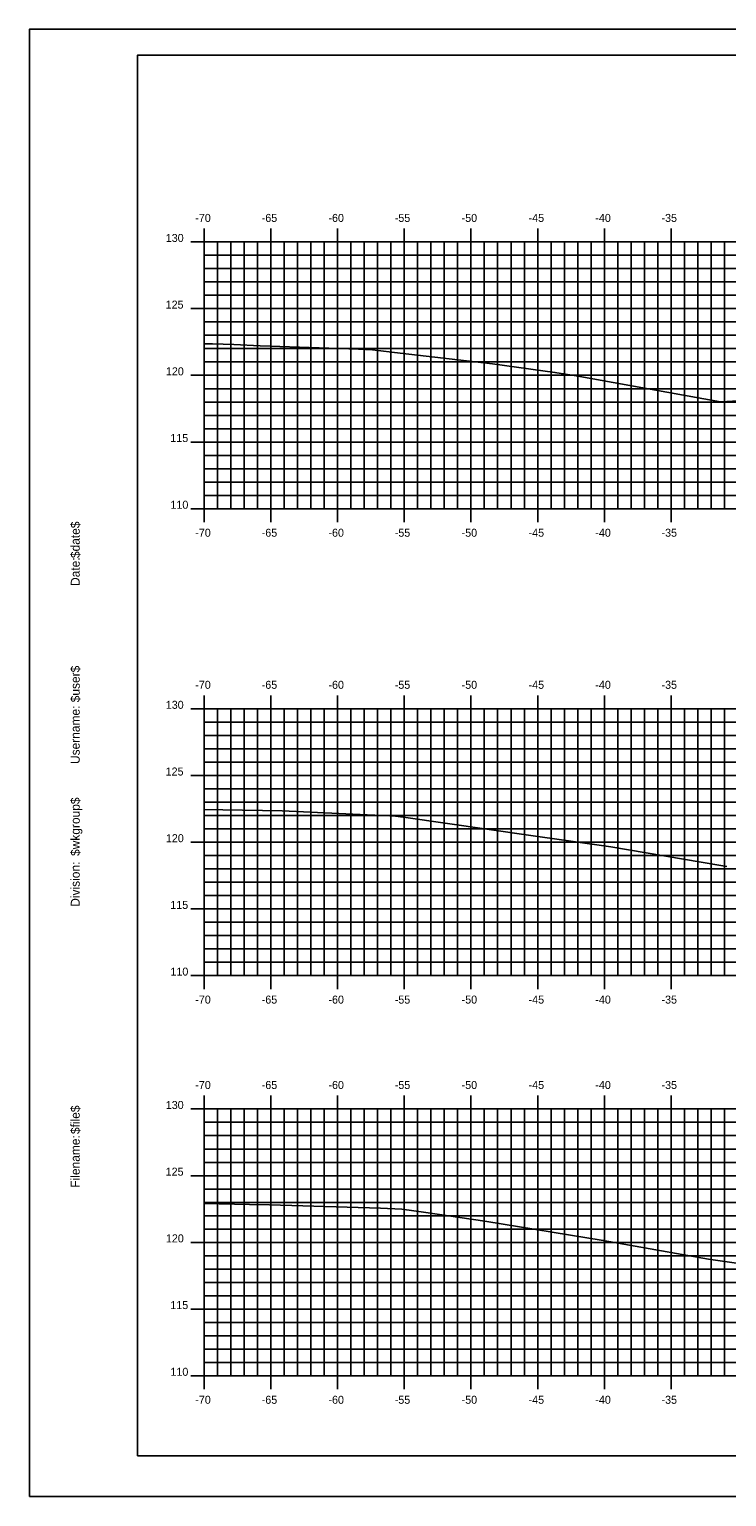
# Model space of a CAD drawing. Extents: x 852625 to 852797, y 365624 to 365734.
# Drawn here: x 852625.5 to 852677.7, y 365624 to 365734 of the extents above; entities that cross this region are included whole.
import ezdxf

# ---------------------------------------------------------------- set-up
doc = ezdxf.new("R2010")
doc.units = 0
for name, color, linetype in [('BORDER', 7, 'Continuous'), ('H_V ANNOTATION', 7, 'Continuous'), ('MAJOR', 7, 'Continuous'), ('MINOR', 7, 'Continuous'), ('PLOT BOUNDARY', 7, 'Continuous'), ('S_Roadway_Centerline', 7, 'Continuous')]:
    doc.layers.add(name, color=color, linetype=linetype)

msp = doc.modelspace()

# ---------------------------------------------------------------- linework, layer by layer
at = {"layer": 'BORDER'}
msp.add_lwpolyline([(852633.55, 365627.03), (852793.55, 365627.03), (852793.55, 365732.03), (852633.55, 365732.03)], close=True, dxfattribs=at)
at = {"layer": 'MAJOR'}
for p, q in [((852638.55, 365719.03), (852638.55, 365718.03)), ((852643.55, 365719.03), (852643.55, 365718.03)), ((852648.55, 365719.03), (852648.55, 365718.03)), ((852653.55, 365719.03), (852653.55, 365718.03)), ((852658.55, 365719.03), (852658.55, 365718.03)), ((852663.55, 365719.03), (852663.55, 365718.03)), ((852668.55, 365719.03), (852668.55, 365718.03)), ((852673.55, 365719.03), (852673.55, 365718.03)), ((852637.55, 365718.03), (852638.55, 365718.03)), ((852638.55, 365718.03), (852778.55, 365718.03)), ((852638.55, 365698.03), (852638.55, 365718.03)), ((852638.55, 365698.03), (852638.55, 365718.03)), ((852638.55, 365718.03), (852778.55, 365718.03)), ((852643.55, 365698.03), (852643.55, 365718.03)), ((852648.55, 365698.03), (852648.55, 365718.03)), ((852653.55, 365698.03), (852653.55, 365718.03)), ((852658.55, 365698.03), (852658.55, 365718.03)), ((852663.55, 365698.03), (852663.55, 365718.03)), ((852668.55, 365698.03), (852668.55, 365718.03)), ((852673.55, 365698.03), (852673.55, 365718.03)), ((852637.55, 365713.03), (852638.55, 365713.03)), ((852638.55, 365713.03), (852778.55, 365713.03)), ((852637.55, 365708.03), (852638.55, 365708.03)), ((852638.55, 365708.03), (852778.55, 365708.03)), ((852637.55, 365703.03), (852638.55, 365703.03)), ((852638.55, 365703.03), (852778.55, 365703.03)), ((852637.55, 365698.03), (852638.55, 365698.03)), ((852638.55, 365698.03), (852778.55, 365698.03)), ((852638.55, 365697.02), (852638.55, 365698.03)), ((852643.55, 365697.02), (852643.55, 365698.03)), ((852648.55, 365697.02), (852648.55, 365698.03)), ((852653.55, 365697.02), (852653.55, 365698.03)), ((852658.55, 365697.02), (852658.55, 365698.03)), ((852663.55, 365697.02), (852663.55, 365698.03)), ((852668.55, 365697.02), (852668.55, 365698.03)), ((852673.55, 365697.02), (852673.55, 365698.03)), ((852638.55, 365684.03), (852638.55, 365683.03)), ((852643.55, 365684.03), (852643.55, 365683.03)), ((852648.55, 365684.03), (852648.55, 365683.03)), ((852653.55, 365684.03), (852653.55, 365683.03)), ((852658.55, 365684.03), (852658.55, 365683.03)), ((852663.55, 365684.03), (852663.55, 365683.03)), ((852668.55, 365684.03), (852668.55, 365683.03)), ((852673.55, 365684.03), (852673.55, 365683.03)), ((852637.55, 365683.03), (852638.55, 365683.03)), ((852638.55, 365683.03), (852778.55, 365683.03)), ((852638.55, 365663.03), (852638.55, 365683.03)), ((852638.55, 365663.03), (852638.55, 365683.03)), ((852638.55, 365683.03), (852778.55, 365683.03)), ((852643.55, 365663.03), (852643.55, 365683.03)), ((852648.55, 365663.03), (852648.55, 365683.03)), ((852653.55, 365663.03), (852653.55, 365683.03)), ((852658.55, 365663.03), (852658.55, 365683.03)), ((852663.55, 365663.03), (852663.55, 365683.03)), ((852668.55, 365663.03), (852668.55, 365683.03)), ((852673.55, 365663.03), (852673.55, 365683.03)), ((852637.55, 365678.03), (852638.55, 365678.03)), ((852638.55, 365678.03), (852778.55, 365678.03)), ((852637.55, 365673.03), (852638.55, 365673.03)), ((852638.55, 365673.03), (852778.55, 365673.03)), ((852637.55, 365668.03), (852638.55, 365668.03)), ((852638.55, 365668.03), (852778.55, 365668.03)), ((852637.55, 365663.03), (852638.55, 365663.03)), ((852638.55, 365663.03), (852778.55, 365663.03)), ((852638.55, 365663.03), (852778.55, 365663.03)), ((852638.55, 365662.02), (852638.55, 365663.03)), ((852643.55, 365662.02), (852643.55, 365663.03)), ((852648.55, 365662.02), (852648.55, 365663.03)), ((852653.55, 365662.02), (852653.55, 365663.03)), ((852658.55, 365662.02), (852658.55, 365663.03)), ((852663.55, 365662.02), (852663.55, 365663.03)), ((852668.55, 365662.02), (852668.55, 365663.03)), ((852673.55, 365662.02), (852673.55, 365663.03)), ((852638.55, 365654.03), (852638.55, 365653.03)), ((852643.55, 365654.03), (852643.55, 365653.03)), ((852648.55, 365654.03), (852648.55, 365653.03)), ((852653.55, 365654.03), (852653.55, 365653.03)), ((852658.55, 365654.03), (852658.55, 365653.03)), ((852663.55, 365654.03), (852663.55, 365653.03)), ((852668.55, 365654.03), (852668.55, 365653.03)), ((852673.55, 365654.03), (852673.55, 365653.03)), ((852637.55, 365653.03), (852638.55, 365653.03)), ((852638.55, 365653.03), (852778.55, 365653.03)), ((852638.55, 365633.03), (852638.55, 365653.03)), ((852638.55, 365633.03), (852638.55, 365653.03)), ((852638.55, 365653.03), (852778.55, 365653.03)), ((852643.55, 365633.03), (852643.55, 365653.03)), ((852648.55, 365633.03), (852648.55, 365653.03)), ((852653.55, 365633.03), (852653.55, 365653.03)), ((852658.55, 365633.03), (852658.55, 365653.03)), ((852663.55, 365633.03), (852663.55, 365653.03)), ((852668.55, 365633.03), (852668.55, 365653.03)), ((852673.55, 365633.03), (852673.55, 365653.03)), ((852637.55, 365648.03), (852638.55, 365648.03)), ((852638.55, 365648.03), (852778.55, 365648.03)), ((852637.55, 365643.03), (852638.55, 365643.03)), ((852638.55, 365643.03), (852778.55, 365643.03)), ((852637.55, 365638.03), (852638.55, 365638.03)), ((852638.55, 365638.03), (852778.55, 365638.03)), ((852637.55, 365633.03), (852638.55, 365633.03)), ((852638.55, 365633.03), (852778.55, 365633.03)), ((852638.55, 365633.03), (852778.55, 365633.03)), ((852638.55, 365632.02), (852638.55, 365633.03)), ((852643.55, 365632.02), (852643.55, 365633.03)), ((852648.55, 365632.02), (852648.55, 365633.03)), ((852653.55, 365632.02), (852653.55, 365633.03)), ((852658.55, 365632.02), (852658.55, 365633.03)), ((852663.55, 365632.02), (852663.55, 365633.03)), ((852668.55, 365632.02), (852668.55, 365633.03)), ((852673.55, 365632.02), (852673.55, 365633.03))]:
    msp.add_line(p, q, dxfattribs=at)
at = {"layer": 'MINOR'}
for p, q in [((852638.55, 365698.03), (852638.55, 365718.03)), ((852638.55, 365717.03), (852778.55, 365717.03)), ((852638.55, 365717.03), (852639.55, 365717.03)), ((852639.55, 365698.03), (852639.55, 365718.03)), ((852640.55, 365698.03), (852640.55, 365718.03)), ((852641.55, 365698.03), (852641.55, 365718.03)), ((852642.55, 365698.03), (852642.55, 365718.03)), ((852644.55, 365698.03), (852644.55, 365718.03)), ((852645.55, 365698.03), (852645.55, 365718.03)), ((852646.55, 365698.03), (852646.55, 365718.03)), ((852647.55, 365698.03), (852647.55, 365718.03)), ((852649.55, 365698.03), (852649.55, 365718.03)), ((852650.55, 365698.03), (852650.55, 365718.03)), ((852651.55, 365698.03), (852651.55, 365718.03)), ((852652.55, 365698.03), (852652.55, 365718.03)), ((852654.55, 365698.03), (852654.55, 365718.03)), ((852655.55, 365698.03), (852655.55, 365718.03)), ((852656.55, 365698.03), (852656.55, 365718.03)), ((852657.55, 365698.03), (852657.55, 365718.03)), ((852659.55, 365698.03), (852659.55, 365718.03)), ((852660.55, 365698.03), (852660.55, 365718.03)), ((852661.55, 365698.03), (852661.55, 365718.03)), ((852662.55, 365698.03), (852662.55, 365718.03)), ((852664.55, 365698.03), (852664.55, 365718.03)), ((852665.55, 365698.03), (852665.55, 365718.03)), ((852666.55, 365698.03), (852666.55, 365718.03)), ((852667.55, 365698.03), (852667.55, 365718.03)), ((852669.55, 365698.03), (852669.55, 365718.03)), ((852670.55, 365698.03), (852670.55, 365718.03)), ((852671.55, 365698.03), (852671.55, 365718.03)), ((852672.55, 365698.03), (852672.55, 365718.03)), ((852674.55, 365698.03), (852674.55, 365718.03)), ((852675.55, 365698.03), (852675.55, 365718.03)), ((852676.55, 365698.03), (852676.55, 365718.03)), ((852677.55, 365698.03), (852677.55, 365718.03)), ((852638.55, 365716.03), (852778.55, 365716.03)), ((852638.55, 365716.03), (852639.55, 365716.03)), ((852638.55, 365715.03), (852778.55, 365715.03)), ((852638.55, 365715.03), (852639.55, 365715.03)), ((852638.55, 365714.03), (852778.55, 365714.03)), ((852638.55, 365714.03), (852639.55, 365714.03)), ((852638.55, 365712.03), (852778.55, 365712.03)), ((852638.55, 365712.03), (852639.55, 365712.03)), ((852638.55, 365711.03), (852778.55, 365711.03)), ((852638.55, 365711.03), (852639.55, 365711.03)), ((852638.55, 365710.03), (852778.55, 365710.03)), ((852638.55, 365710.03), (852639.55, 365710.03)), ((852638.55, 365709.03), (852778.55, 365709.03)), ((852638.55, 365709.03), (852639.55, 365709.03)), ((852638.55, 365707.03), (852778.55, 365707.03)), ((852638.55, 365707.03), (852639.55, 365707.03)), ((852638.55, 365706.03), (852778.55, 365706.03)), ((852638.55, 365706.03), (852639.55, 365706.03)), ((852638.55, 365705.03), (852778.55, 365705.03)), ((852638.55, 365705.03), (852639.55, 365705.03)), ((852638.55, 365704.03), (852778.55, 365704.03)), ((852638.55, 365704.03), (852639.55, 365704.03)), ((852638.55, 365702.03), (852778.55, 365702.03)), ((852638.55, 365702.03), (852639.55, 365702.03)), ((852638.55, 365701.03), (852778.55, 365701.03)), ((852638.55, 365701.03), (852639.55, 365701.03)), ((852638.55, 365700.03), (852778.55, 365700.03)), ((852638.55, 365700.03), (852639.55, 365700.03)), ((852638.55, 365699.03), (852778.55, 365699.03)), ((852638.55, 365699.03), (852639.55, 365699.03)), ((852639.55, 365663.03), (852639.55, 365683.03)), ((852640.55, 365663.03), (852640.55, 365683.03)), ((852641.55, 365663.03), (852641.55, 365683.03)), ((852642.55, 365663.03), (852642.55, 365683.03)), ((852644.55, 365663.03), (852644.55, 365683.03)), ((852645.55, 365663.03), (852645.55, 365683.03)), ((852646.55, 365663.03), (852646.55, 365683.03)), ((852647.55, 365663.03), (852647.55, 365683.03)), ((852649.55, 365663.03), (852649.55, 365683.03)), ((852650.55, 365663.03), (852650.55, 365683.03)), ((852651.55, 365663.03), (852651.55, 365683.03)), ((852652.55, 365663.03), (852652.55, 365683.03)), ((852654.55, 365663.03), (852654.55, 365683.03)), ((852655.55, 365663.03), (852655.55, 365683.03)), ((852656.55, 365663.03), (852656.55, 365683.03)), ((852657.55, 365663.03), (852657.55, 365683.03)), ((852659.55, 365663.03), (852659.55, 365683.03)), ((852660.55, 365663.03), (852660.55, 365683.03)), ((852661.55, 365663.03), (852661.55, 365683.03)), ((852662.55, 365663.03), (852662.55, 365683.03)), ((852664.55, 365663.03), (852664.55, 365683.03)), ((852665.55, 365663.03), (852665.55, 365683.03)), ((852666.55, 365663.03), (852666.55, 365683.03)), ((852667.55, 365663.03), (852667.55, 365683.03)), ((852669.55, 365663.03), (852669.55, 365683.03)), ((852670.55, 365663.03), (852670.55, 365683.03)), ((852671.55, 365663.03), (852671.55, 365683.03)), ((852672.55, 365663.03), (852672.55, 365683.03)), ((852674.55, 365663.03), (852674.55, 365683.03)), ((852675.55, 365663.03), (852675.55, 365683.03)), ((852676.55, 365663.03), (852676.55, 365683.03)), ((852677.55, 365663.03), (852677.55, 365683.03)), ((852638.55, 365682.03), (852778.55, 365682.03)), ((852638.55, 365682.03), (852639.55, 365682.03)), ((852638.55, 365681.03), (852778.55, 365681.03)), ((852638.55, 365681.03), (852639.55, 365681.03)), ((852638.55, 365680.03), (852778.55, 365680.03)), ((852638.55, 365680.03), (852639.55, 365680.03)), ((852638.55, 365679.03), (852778.55, 365679.03)), ((852638.55, 365679.03), (852639.55, 365679.03)), ((852638.55, 365677.03), (852778.55, 365677.03)), ((852638.55, 365677.03), (852639.55, 365677.03)), ((852638.55, 365676.03), (852778.55, 365676.03)), ((852638.55, 365676.03), (852639.55, 365676.03)), ((852638.55, 365675.03), (852778.55, 365675.03)), ((852638.55, 365675.03), (852639.55, 365675.03)), ((852638.55, 365674.03), (852778.55, 365674.03)), ((852638.55, 365674.03), (852639.55, 365674.03)), ((852638.55, 365672.03), (852778.55, 365672.03)), ((852638.55, 365672.03), (852639.55, 365672.03)), ((852638.55, 365671.03), (852778.55, 365671.03)), ((852638.55, 365671.03), (852639.55, 365671.03)), ((852638.55, 365670.03), (852778.55, 365670.03)), ((852638.55, 365670.03), (852639.55, 365670.03)), ((852638.55, 365669.03), (852778.55, 365669.03)), ((852638.55, 365669.03), (852639.55, 365669.03)), ((852638.55, 365667.03), (852778.55, 365667.03)), ((852638.55, 365667.03), (852639.55, 365667.03)), ((852638.55, 365666.03), (852778.55, 365666.03)), ((852638.55, 365666.03), (852639.55, 365666.03)), ((852638.55, 365665.03), (852778.55, 365665.03)), ((852638.55, 365665.03), (852639.55, 365665.03)), ((852638.55, 365664.03), (852778.55, 365664.03)), ((852638.55, 365664.03), (852639.55, 365664.03)), ((852639.55, 365633.03), (852639.55, 365653.03)), ((852640.55, 365633.03), (852640.55, 365653.03)), ((852641.55, 365633.03), (852641.55, 365653.03)), ((852642.55, 365633.03), (852642.55, 365653.03)), ((852644.55, 365633.03), (852644.55, 365653.03)), ((852645.55, 365633.03), (852645.55, 365653.03)), ((852646.55, 365633.03), (852646.55, 365653.03)), ((852647.55, 365633.03), (852647.55, 365653.03)), ((852649.55, 365633.03), (852649.55, 365653.03)), ((852650.55, 365633.03), (852650.55, 365653.03)), ((852651.55, 365633.03), (852651.55, 365653.03)), ((852652.55, 365633.03), (852652.55, 365653.03)), ((852654.55, 365633.03), (852654.55, 365653.03)), ((852655.55, 365633.03), (852655.55, 365653.03)), ((852656.55, 365633.03), (852656.55, 365653.03)), ((852657.55, 365633.03), (852657.55, 365653.03)), ((852659.55, 365633.03), (852659.55, 365653.03)), ((852660.55, 365633.03), (852660.55, 365653.03)), ((852661.55, 365633.03), (852661.55, 365653.03)), ((852662.55, 365633.03), (852662.55, 365653.03)), ((852664.55, 365633.03), (852664.55, 365653.03)), ((852665.55, 365633.03), (852665.55, 365653.03)), ((852666.55, 365633.03), (852666.55, 365653.03)), ((852667.55, 365633.03), (852667.55, 365653.03)), ((852669.55, 365633.03), (852669.55, 365653.03)), ((852670.55, 365633.03), (852670.55, 365653.03)), ((852671.55, 365633.03), (852671.55, 365653.03)), ((852672.55, 365633.03), (852672.55, 365653.03)), ((852674.55, 365633.03), (852674.55, 365653.03)), ((852675.55, 365633.03), (852675.55, 365653.03)), ((852676.55, 365633.03), (852676.55, 365653.03)), ((852677.55, 365633.03), (852677.55, 365653.03)), ((852638.55, 365652.03), (852778.55, 365652.03)), ((852638.55, 365652.03), (852639.55, 365652.03)), ((852638.55, 365651.03), (852778.55, 365651.03)), ((852638.55, 365651.03), (852639.55, 365651.03)), ((852638.55, 365650.03), (852778.55, 365650.03)), ((852638.55, 365650.03), (852639.55, 365650.03)), ((852638.55, 365649.03), (852778.55, 365649.03)), ((852638.55, 365649.03), (852639.55, 365649.03)), ((852638.55, 365647.03), (852778.55, 365647.03)), ((852638.55, 365647.03), (852639.55, 365647.03)), ((852638.55, 365646.03), (852778.55, 365646.03)), ((852638.55, 365646.03), (852639.55, 365646.03)), ((852638.55, 365645.03), (852778.55, 365645.03)), ((852638.55, 365645.03), (852639.55, 365645.03)), ((852638.55, 365644.03), (852778.55, 365644.03)), ((852638.55, 365644.03), (852639.55, 365644.03)), ((852638.55, 365642.03), (852778.55, 365642.03)), ((852638.55, 365642.03), (852639.55, 365642.03)), ((852638.55, 365641.03), (852778.55, 365641.03)), ((852638.55, 365641.03), (852639.55, 365641.03)), ((852638.55, 365640.03), (852778.55, 365640.03)), ((852638.55, 365640.03), (852639.55, 365640.03)), ((852638.55, 365639.03), (852778.55, 365639.03)), ((852638.55, 365639.03), (852639.55, 365639.03)), ((852638.55, 365637.03), (852778.55, 365637.03)), ((852638.55, 365637.03), (852639.55, 365637.03)), ((852638.55, 365636.03), (852778.55, 365636.03)), ((852638.55, 365636.03), (852639.55, 365636.03)), ((852638.55, 365635.03), (852778.55, 365635.03)), ((852638.55, 365635.03), (852639.55, 365635.03)), ((852638.55, 365634.03), (852778.55, 365634.03)), ((852638.55, 365634.03), (852639.55, 365634.03))]:
    msp.add_line(p, q, dxfattribs=at)
at = {"layer": 'PLOT BOUNDARY'}
msp.add_lwpolyline([(852625.46, 365623.97), (852795.46, 365623.97), (852795.46, 365733.97), (852625.46, 365733.97)], close=True, dxfattribs=at)
at = {"layer": 'S_Roadway_Centerline'}
for points in [[(852638.55, 365710.39), (852639.18, 365710.38), (852640.79, 365710.35), (852642.74, 365710.25), (852650.13, 365710), (852651.16, 365709.95), (852653.24, 365709.7), (852660.17, 365708.88), (852664.84, 365708.25), (852666.43, 365707.98), (852677.25, 365706.05), (852677.27, 365706.05), (852682.14, 365706.33), (852690.94, 365707.08), (852704.81, 365708.54), (852709.58, 365708.97), (852711.4, 365709.11), (852723.49, 365709.8), (852723.5, 365709.78), (852729.09, 365710.02), (852733.32, 365710.17), (852739.79, 365710.32)], [(852638.55, 365675.48), (852639.96, 365675.46), (852644.4, 365675.39), (852650.76, 365675.07), (852652.48, 365675.01), (852652.69, 365675), (852653.68, 365674.88), (852662.87, 365673.56), (852669.03, 365672.69), (852677.12, 365671.31), (852677.72, 365671.2)], [(852638.55, 365645.95), (852641.96, 365645.86), (852643.44, 365645.84), (852651.78, 365645.6), (852653.37, 365645.53), (852654.99, 365645.29), (852659.59, 365644.62), (852668.46, 365643.18), (852676.35, 365641.78), (852678.44, 365641.46), (852678.74, 365641.39), (852679.61, 365641.47), (852690.32, 365642.46), (852697.76, 365643.31), (852702.54, 365643.83), (852709.5, 365644.44), (852716.87, 365645.07), (852723.2, 365645.51), (852723.7, 365645.5), (852735.72, 365645.82), (852736.97, 365645.86), (852738.03, 365645.89)]]:
    msp.add_lwpolyline(points, dxfattribs=at)

# ---------------------------------------------------------------- texts
at = {"layer": 'BORDER'}
for s, p in [('$date$', (852629.23, 365694.33)), ('Date:', (852629.23, 365692.24)), ('$user$', (852629.23, 365683.52)), ('Username:', (852629.23, 365678.89)), ('$wkgroup$', (852629.23, 365672)), ('Division:', (852629.23, 365668.19)), ('$file$', (852629.23, 365651.15)), ('Filename:', (852629.23, 365647.13))]:
    msp.add_text(s, height=0.67, rotation=90, dxfattribs=at).set_placement(p)
at = {"layer": 'H_V ANNOTATION'}
for s, p in [('-70', (852637.89, 365719.53)), ('-65', (852642.87, 365719.53)), ('-60', (852647.87, 365719.53)), ('-55', (852652.84, 365719.53)), ('-50', (852657.85, 365719.53)), ('-45', (852662.87, 365719.53)), ('-40', (852667.87, 365719.53)), ('-35', (852672.83, 365719.53)), ('130', (852635.68, 365718.03)), ('125', (852635.67, 365713.03)), ('120', (852635.69, 365708.03)), ('115', (852636.02, 365703.03)), ('110', (852636.03, 365698.03)), ('-70', (852637.89, 365695.93)), ('-65', (852642.87, 365695.93)), ('-60', (852647.87, 365695.93)), ('-55', (852652.84, 365695.93)), ('-50', (852657.85, 365695.93)), ('-45', (852662.87, 365695.93)), ('-40', (852667.87, 365695.93)), ('-35', (852672.83, 365695.93)), ('-70', (852637.89, 365684.53)), ('-65', (852642.87, 365684.53)), ('-60', (852647.87, 365684.53)), ('-55', (852652.84, 365684.53)), ('-50', (852657.85, 365684.53)), ('-45', (852662.87, 365684.53)), ('-40', (852667.87, 365684.53)), ('-35', (852672.83, 365684.53)), ('130', (852635.68, 365683.03)), ('125', (852635.67, 365678.03)), ('120', (852635.69, 365673.03)), ('115', (852636.02, 365668.03)), ('110', (852636.03, 365663.03)), ('-70', (852637.89, 365660.93)), ('-65', (852642.87, 365660.93)), ('-60', (852647.87, 365660.93)), ('-55', (852652.84, 365660.93)), ('-50', (852657.85, 365660.93)), ('-45', (852662.87, 365660.93)), ('-40', (852667.87, 365660.93)), ('-35', (852672.83, 365660.93)), ('-70', (852637.89, 365654.53)), ('-65', (852642.87, 365654.53)), ('-60', (852647.87, 365654.53)), ('-55', (852652.84, 365654.53)), ('-50', (852657.85, 365654.53)), ('-45', (852662.87, 365654.53)), ('-40', (852667.87, 365654.53)), ('-35', (852672.83, 365654.53)), ('130', (852635.68, 365653.03)), ('125', (852635.67, 365648.03)), ('120', (852635.69, 365643.03)), ('115', (852636.02, 365638.03)), ('110', (852636.03, 365633.03)), ('-70', (852637.89, 365630.93)), ('-65', (852642.87, 365630.93)), ('-60', (852647.87, 365630.93)), ('-55', (852652.84, 365630.93)), ('-50', (852657.85, 365630.93)), ('-45', (852662.87, 365630.93)), ('-40', (852667.87, 365630.93)), ('-35', (852672.83, 365630.93))]:
    msp.add_text(s, height=0.6, dxfattribs=at).set_placement(p)
at = {"layer": 'MAJOR'}
for p in [(852638.54, 365698.03), (852638.54, 365663.03), (852638.54, 365633.03)]:
    msp.add_text('-', height=0.006, dxfattribs=at).set_placement(p)

doc.saveas('drawing.dxf')
